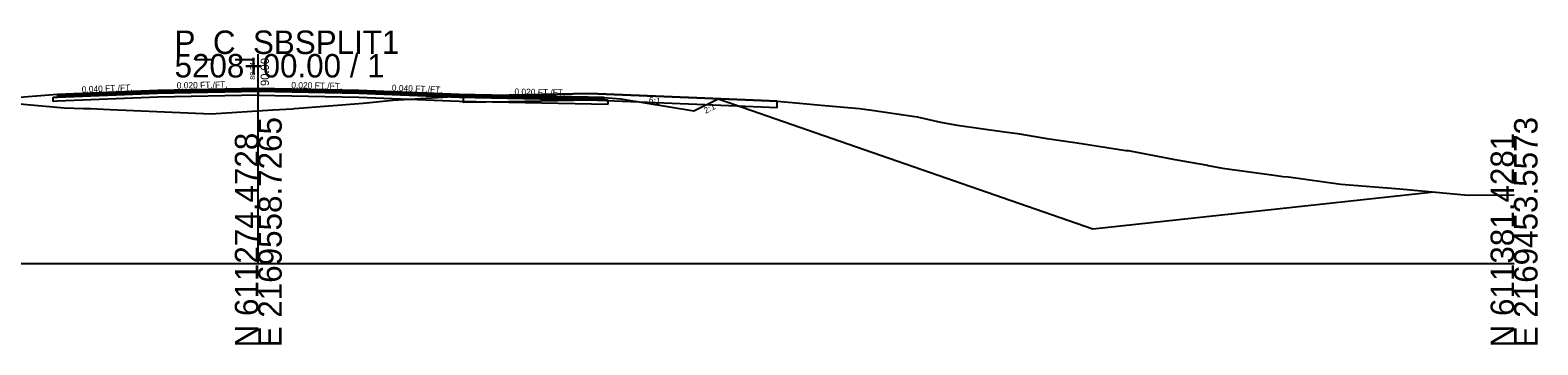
# Model space of a CAD drawing. Extents: x -26 to 1303, y -3010 to 12033.
# Drawn here: x 1122.8 to 1302.8, y 5990.3 to 6027.8 of the extents above; entities that cross this region are included whole.
import ezdxf

# ---------------------------------------------------------------- set-up
doc = ezdxf.new("R2010")
doc.units = 0
for name, color, linetype in [('RD_GPK_XS_Cell', 7, 'Continuous'), ('RD_Sketch10', 7, 'Continuous'), ('RD_XS_Base', 7, 'Continuous'), ('RD_XS_ExGround', 7, 'Continuous'), ('RD_XS_ExPaveRet', 7, 'Continuous'), ('RD_XS_Greenside', 7, 'Continuous'), ('RD_XS_Pave', 7, 'Continuous'), ('RD_XS_PaveOvlay_CP', 7, 'Continuous'), ('RD_XS_TieSlope', 7, 'Continuous'), ('RD_XS_TX_Elev_EX', 7, 'Continuous'), ('RD_XS_TX_Elev_PR', 7, 'Continuous'), ('RD_XS_TX_Slope', 7, 'Continuous')]:
    doc.layers.add(name, color=color, linetype=linetype)

msp = doc.modelspace()

# ---------------------------------------------------------------- linework, layer by layer
at = {"layer": 'RD_GPK_XS_Cell'}
for p, q in [((1150, 6000), (1150, 6025)), ((1000, 6000), (1150, 6000)), ((1150, 6000), (1300, 6000))]:
    msp.add_line(p, q, dxfattribs=at)
at = {"layer": 'RD_Sketch10'}
msp.add_lwpolyline([(1204.93, 6019.67), (1249.67, 6004.14), (1290.43, 6008.54)], dxfattribs=at)
at = {"layer": 'RD_XS_Base'}
for p, q in [((1138, 6020.34), (1150, 6020.58)), ((1150, 6020.58), (1150, 6020.74)), ((1150, 6020.74), (1150, 6020.08)), ((1150, 6020.58), (1150, 6020.08)), ((1150, 6020.58), (1150, 6020.58)), ((1162, 6020.34), (1150, 6020.58)), ((1150, 6020.58), (1150, 6020.58)), ((1125.5, 6019.84), (1126, 6019.86)), ((1125.5, 6019.34), (1125.5, 6019.84)), ((1125.5, 6019.84), (1125.5, 6019.84)), ((1126, 6019.36), (1125.5, 6019.34)), ((1125.5, 6019.34), (1125.5, 6019.34)), ((1125.5, 6019.34), (1125.5, 6019.34)), ((1126, 6019.86), (1138, 6020.34)), ((1126, 6019.86), (1126, 6019.86)), ((1138, 6019.84), (1126, 6019.36)), ((1126, 6019.36), (1126, 6019.36)), ((1136, 6020.26), (1136, 6020.26)), ((1136, 6019.76), (1136, 6019.76)), ((1150, 6020.08), (1138, 6019.84)), ((1150, 6020.08), (1150, 6020.08)), ((1150, 6020.08), (1150, 6020.08)), ((1150, 6020.08), (1162, 6019.84)), ((1174, 6019.86), (1162, 6020.34)), ((1162, 6020.34), (1162, 6020.34)), ((1162, 6019.84), (1162, 6019.84)), ((1162, 6019.84), (1174, 6019.36)), ((1191.3, 6019.51), (1174, 6019.86)), ((1174, 6019.86), (1174, 6019.86)), ((1174, 6019.36), (1174, 6019.36)), ((1174, 6019.36), (1191.8, 6019)), ((1191.8, 6019.5), (1191.3, 6019.51)), ((1191.3, 6019.51), (1191.3, 6019.51)), ((1191.8, 6019), (1191.8, 6019.5)), ((1191.8, 6019.5), (1191.8, 6019.5)), ((1191.8, 6019), (1191.8, 6019)), ((1191.8, 6019), (1191.8, 6019))]:
    msp.add_line(p, q, dxfattribs=at)
at = {"layer": 'RD_XS_ExGround'}
msp.add_lwpolyline([(1110.42, 6020.07), (1126.8, 6018.57), (1129.12, 6018.5), (1129.97, 6018.5), (1132.31, 6018.38), (1144.37, 6017.87), (1151.74, 6018.35), (1154.09, 6018.46), (1154.32, 6018.49), (1162.53, 6019.13), (1166.07, 6019.51), (1173.35, 6019.94), (1174.49, 6019.99), (1179.96, 6020.1), (1189.56, 6020.3), (1202.39, 6019.77), (1211.98, 6019.38), (1214.65, 6019.12), (1217.69, 6018.87), (1221.81, 6018.5), (1223.27, 6018.29), (1228.69, 6017.5), (1231.5, 6016.88), (1233.46, 6016.52), (1239.13, 6015.73), (1240.7, 6015.5), (1244.19, 6014.91), (1247.8, 6014.4), (1253.63, 6013.5), (1253.89, 6013.49), (1259.47, 6012.42), (1263.37, 6011.73), (1263.48, 6011.7), (1265.19, 6011.38), (1271.64, 6010.5), (1272.38, 6010.4), (1273.06, 6010.33), (1279.31, 6009.49), (1286.35, 6008.91), (1294.5, 6008.17), (1300, 6008.18)], dxfattribs=at)
at = {"layer": 'RD_XS_ExPaveRet'}
for points in [[(1211.98, 6019.38), (1202.39, 6019.77), (1202.39, 6019.77), (1189.56, 6020.3), (1189.56, 6020.3), (1179.96, 6020.1), (1179.96, 6020.1), (1174.49, 6019.99), (1174.49, 6019.99), (1174.49, 6019.24), (1174.49, 6019.24), (1174.49, 6019.24), (1179.96, 6019.35), (1179.96, 6019.35), (1189.56, 6019.55), (1189.56, 6019.55), (1202.39, 6019.02), (1202.39, 6019.02), (1211.98, 6018.63), (1211.98, 6018.63), (1211.98, 6018.63), (1211.98, 6019.38), (1211.98, 6019.38)], [(1211.98, 6019.38), (1202.39, 6019.77), (1189.56, 6020.3), (1179.96, 6020.1), (1174.49, 6019.99), (1174.49, 6019.99), (1174.49, 6019.24), (1174.49, 6019.24), (1179.96, 6019.35), (1189.56, 6019.55), (1202.39, 6019.02), (1211.98, 6018.63), (1211.98, 6019.38)]]:
    msp.add_lwpolyline(points, dxfattribs=at)
at = {"layer": 'RD_XS_Greenside'}
for p, q in [((1193.3, 6019.67), (1202.03, 6018.22)), ((1202.03, 6018.22), (1204.93, 6019.67))]:
    msp.add_line(p, q, dxfattribs=at)
at = {"layer": 'RD_XS_Pave'}
for p, q in [((1138, 6020.66), (1126, 6020.18)), ((1138, 6020.5), (1126, 6020.02)), ((1126, 6020.02), (1138, 6020.5)), ((1136, 6020.58), (1136, 6020.58)), ((1136, 6020.42), (1136, 6020.42)), ((1136, 6020.42), (1136, 6020.42)), ((1150, 6020.9), (1138, 6020.66)), ((1150, 6020.74), (1138, 6020.5)), ((1138, 6020.5), (1150, 6020.74)), ((1138, 6020.34), (1150, 6020.58)), ((1162, 6020.66), (1150, 6020.9)), ((1150, 6020.58), (1150, 6020.74)), ((1150, 6020.74), (1162, 6020.5)), ((1162, 6020.5), (1150, 6020.74)), ((1150, 6020.74), (1150, 6020.74)), ((1150, 6020.74), (1150, 6020.58)), ((1150, 6020.58), (1150, 6020.58)), ((1150, 6020.58), (1150, 6020.58)), ((1150, 6020.58), (1150, 6020.58)), ((1150, 6020.58), (1162, 6020.34)), ((1174, 6020.18), (1162, 6020.66)), ((1162, 6020.66), (1162, 6020.66)), ((1162, 6020.5), (1162, 6020.5)), ((1162, 6020.5), (1174, 6020.02)), ((1174, 6020.02), (1162, 6020.5)), ((1162, 6020.5), (1162, 6020.5)), ((1126, 6019.86), (1138, 6020.34)), ((1126, 6020.18), (1126, 6020.18)), ((1126, 6020.18), (1126, 6020.02)), ((1126, 6020.02), (1126, 6020.02)), ((1126, 6020.02), (1126, 6019.86)), ((1126, 6020.02), (1126, 6020.02)), ((1126, 6020.02), (1126, 6020.02)), ((1126, 6019.86), (1126, 6019.86)), ((1126, 6019.86), (1126, 6019.86)), ((1136, 6020.26), (1136, 6020.26)), ((1162, 6020.34), (1162, 6020.34)), ((1162, 6020.34), (1174, 6019.86)), ((1191.3, 6019.83), (1174, 6020.18)), ((1174, 6020.18), (1174, 6020.18)), ((1174, 6020.02), (1174, 6020.02)), ((1174, 6020.02), (1191.3, 6019.67)), ((1191.3, 6019.67), (1174, 6020.02)), ((1174, 6020.02), (1174, 6020.02)), ((1174, 6019.86), (1174, 6019.86)), ((1174, 6019.86), (1191.3, 6019.51)), ((1191.3, 6019.67), (1191.3, 6019.83)), ((1191.3, 6019.83), (1191.3, 6019.83)), ((1191.3, 6019.67), (1191.3, 6019.67)), ((1191.3, 6019.67), (1191.3, 6019.67)), ((1191.3, 6019.51), (1191.3, 6019.67)), ((1191.3, 6019.67), (1191.3, 6019.67)), ((1191.3, 6019.51), (1191.3, 6019.51)), ((1191.3, 6019.51), (1191.3, 6019.51))]:
    msp.add_line(p, q, dxfattribs=at)
at = {"layer": 'RD_XS_PaveOvlay_CP'}
for p, q in [((1138, 6020.66), (1126, 6020.18)), ((1136, 6020.58), (1136, 6020.58)), ((1150, 6020.9), (1138, 6020.66)), ((1162, 6020.66), (1150, 6020.9)), ((1174, 6020.18), (1162, 6020.66)), ((1162, 6020.66), (1162, 6020.66)), ((1126, 6020.18), (1126, 6020.18)), ((1191.3, 6019.83), (1174, 6020.18)), ((1174, 6020.18), (1174, 6020.18)), ((1191.3, 6019.83), (1191.3, 6019.83))]:
    msp.add_line(p, q, dxfattribs=at)
at = {"layer": 'RD_XS_TieSlope'}
for p, q in [((1126, 6020.18), (1120, 6019.7)), ((1191.3, 6019.83), (1193.3, 6019.67))]:
    msp.add_line(p, q, dxfattribs=at)

# ---------------------------------------------------------------- texts
at = {"layer": 'RD_GPK_XS_Cell'}
for s, p in [('P_C_SBSPLIT1', (1140, 6025)), ('5208+00.00 / 1', (1140, 6022.2))]:
    msp.add_text(s, height=2.8, dxfattribs=at).set_placement(p)
for s, p in [('E 2169558.7265', (1152.8, 5990)), ('E 2169453.5573', (1302.8, 5990)), ('N 611274.4728', (1150, 5990)), ('N 611381.4281', (1300, 5990))]:
    msp.add_text(s, height=2.8, rotation=90, dxfattribs=at).set_placement(p)
at = {"layer": 'RD_XS_TX_Elev_EX'}
msp.add_text('88.24', height=0.6, rotation=90, dxfattribs=at).set_placement((1149.62, 6021.94))
at = {"layer": 'RD_XS_TX_Elev_PR'}
msp.add_text('90.90', height=1, rotation=90, dxfattribs=at).set_placement((1151.28, 6021.18))
at = {"layer": 'RD_XS_TX_Slope'}
for s, rotation, p in [('0.040 FT./FT.', 2.2906, (1128.93, 6020.39)), ('0.020 FT./FT.', 1.1458, (1140.27, 6020.87)), ('0.020 FT./FT.', 358.8542, (1153.94, 6020.92)), ('0.040 FT./FT.', 357.7094, (1165.94, 6020.6)), ('0.020 FT./FT.', 358.8542, (1180.59, 6020.14)), ('6:1', 350.5377, (1196.6, 6019.18)), ('2:1', 26.5651, (1203.44, 6017.86))]:
    msp.add_text(s, height=0.75, rotation=rotation, dxfattribs=at).set_placement(p)

doc.saveas('drawing.dxf')
